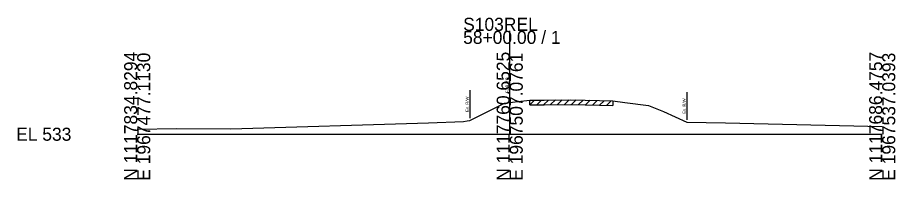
# Model space of a CAD drawing. Extents: x -26 to 163, y -10 to 24518.
# Drawn here: x -25.7 to 162.8, y 8490.3 to 8525 of the extents above; entities that cross this region are included whole.
import ezdxf

# ---------------------------------------------------------------- set-up
doc = ezdxf.new("R2010")
doc.units = 0
for name, color, linetype in [('RD_GPK_XS_Cell', 7, 'Continuous'), ('RD_XS_ExGround', 7, 'Continuous'), ('RD_XS_ExPaveRet', 7, 'Continuous'), ('RD_XS_ExRW', 7, 'Continuous'), ('RD_XS_TX_Elev_EX', 7, 'Continuous')]:
    doc.layers.add(name, color=color, linetype=linetype)

msp = doc.modelspace()

# ---------------------------------------------------------------- linework, layer by layer
at = {"layer": 'RD_GPK_XS_Cell'}
for p, q in [((80, 8500), (80, 8522.17)), ((0, 8500), (80, 8500)), ((80, 8500), (160, 8500))]:
    msp.add_line(p, q, dxfattribs=at)
at = {"layer": 'RD_XS_ExGround'}
msp.add_lwpolyline([(0, 8501.05), (8.54, 8501.22), (20.11, 8501.15), (62.56, 8502.45), (70.11, 8502.76), (70.89, 8502.87), (71.45, 8502.95), (73.76, 8504.11), (78.9, 8506.66), (80, 8506.79), (82.39, 8507.07), (84.29, 8507.29), (87.43, 8507.32), (93.1, 8507.39), (99.26, 8507.22), (102.17, 8507.13), (104.71, 8506.82), (109.84, 8506.18), (113.05, 8504.84), (118.07, 8502.55), (126.33, 8502.41), (160, 8501.67)], dxfattribs=at)
at = {"layer": 'RD_XS_ExPaveRet'}
for p, q in [((84.29, 8506.29), (85.3, 8507.3)), ((84.29, 8506.29), (84.29, 8507.29)), ((85.79, 8506.31), (86.8, 8507.32)), ((87.29, 8506.32), (88.3, 8507.33)), ((88.79, 8506.34), (89.8, 8507.35)), ((90.29, 8506.36), (91.3, 8507.37)), ((91.79, 8506.38), (92.8, 8507.39)), ((93.29, 8506.39), (94.26, 8507.36)), ((94.79, 8506.34), (95.76, 8507.32)), ((96.29, 8506.3), (97.26, 8507.27)), ((97.79, 8506.26), (98.76, 8507.23)), ((99.29, 8506.22), (100.26, 8507.19)), ((100.79, 8506.17), (101.76, 8507.14)), ((102.17, 8507.13), (102.17, 8506.13)), ((84.29, 8506.29), (87.43, 8506.32)), ((87.43, 8506.32), (93.1, 8506.39)), ((93.1, 8506.39), (99.26, 8506.22)), ((99.26, 8506.22), (102.17, 8506.13))]:
    msp.add_line(p, q, dxfattribs=at)
at = {"layer": 'RD_XS_ExRW'}
for p, q in [((71.45, 8509.45), (71.45, 8503.45)), ((71.45, 8509.45), (71.45, 8503.45)), ((118.07, 8509.05), (118.07, 8503.05))]:
    msp.add_line(p, q, dxfattribs=at)

# ---------------------------------------------------------------- texts
at = {"layer": 'RD_GPK_XS_Cell'}
for s, p in [('S103REL', (70, 8522.17)), ('58+00.00 / 1', (70, 8519.37)), ('EL 533', (-26, 8498.6))]:
    msp.add_text(s, height=2.8, dxfattribs=at).set_placement(p)
for s, p in [('N 1117834.8294', (0, 8490)), ('E 1967477.1130', (2.8, 8490)), ('N 1117760.6525', (80, 8490)), ('E 1967507.0761', (82.8, 8490)), ('N 1117686.4757', (160, 8490)), ('E 1967537.0393', (162.8, 8490))]:
    msp.add_text(s, height=2.8, rotation=90, dxfattribs=at).set_placement(p)
at = {"layer": 'RD_XS_ExRW'}
for p in [(71.2, 8504.79), (71.2, 8504.79), (117.82, 8504.39)]:
    msp.add_text('Ex. R/W ', height=0.65, rotation=90, dxfattribs=at).set_placement(p)
at = {"layer": 'RD_XS_TX_Elev_EX'}
msp.add_text('539.79', height=0.8, rotation=90, dxfattribs=at).set_placement((79.9, 8508.79))

doc.saveas('drawing.dxf')
